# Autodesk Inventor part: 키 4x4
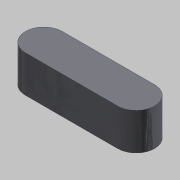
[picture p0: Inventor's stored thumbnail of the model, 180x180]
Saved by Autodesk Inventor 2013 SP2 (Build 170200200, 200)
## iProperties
Created: 2016-04
Part Number: 키 4x4
Document SubType Name: Modeling
Designer: mdu
Density: 1 g/cm^3
Mass: 0.210265 g
Surface Area: 2.35398 cm^2
Volume: 0.210265 cm^3
Material: 강철, 연강
Author: mdu
Revision Number: 1
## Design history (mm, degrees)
sketch "스케치1"
  geometry: L1 (-5, -2)-(5, -2); L2 (5, 2)-(-5, 2); A1 r 2 centre (5, 0) between (5, -2) and (5, 2); A2 r 2 centre (-5, 0) between (-5, 2) and (-5, -2); 2 further points
  constraints: 4 end point, 4 point on circle, 4 tangent, 2 centre point, 1 horizontal, 1 horizontal alignment, 1 midpoint, 1 parallel, 1 vertical alignment
  dimensions: "d0" = 4 distance between parallel lines of L1 L2; "d1" = 14 dimension on A1 A2
extrude "돌출1" new body sketch "스케치1" stored distance "d2" = 4; taper "d3" = 0 deg
node "솔리드1"
